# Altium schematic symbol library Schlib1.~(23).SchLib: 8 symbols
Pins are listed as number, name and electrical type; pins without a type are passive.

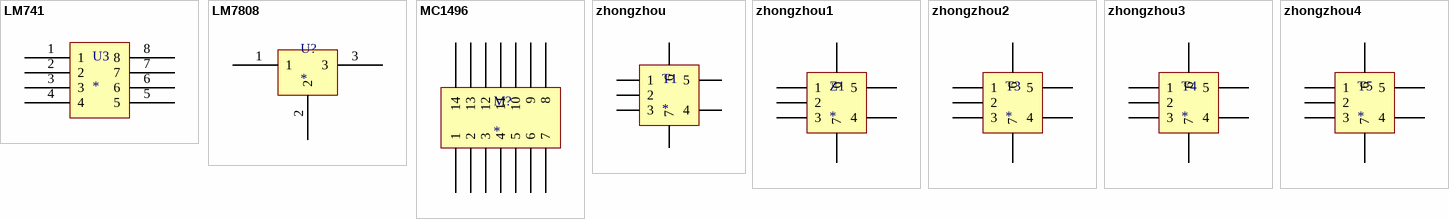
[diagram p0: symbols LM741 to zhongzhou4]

## LM741
designator U3
pins: 1, 2, 3, 4, 5, 6, 7, 8

## LM7808
designator U?
pins: 1, 2, 3

## MC1496
designator M?
pins: 1, 2, 3, 4, 5, 6, 7, 8, 9, 10, 11, 12, 13, 14

## zhongzhou
designator T1
pins: 1, 2, 3, 4, 5, 6, 7

## zhongzhou1
designator Z1
pins: 1, 2, 3, 4, 5, 6, 7

## zhongzhou2
designator T3
pins: 1, 2, 3, 4, 5, 6, 7

## zhongzhou3
designator T4
pins: 1, 2, 3, 4, 5, 6, 7

## zhongzhou4
designator T5
pins: 1, 2, 3, 4, 5, 6, 7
